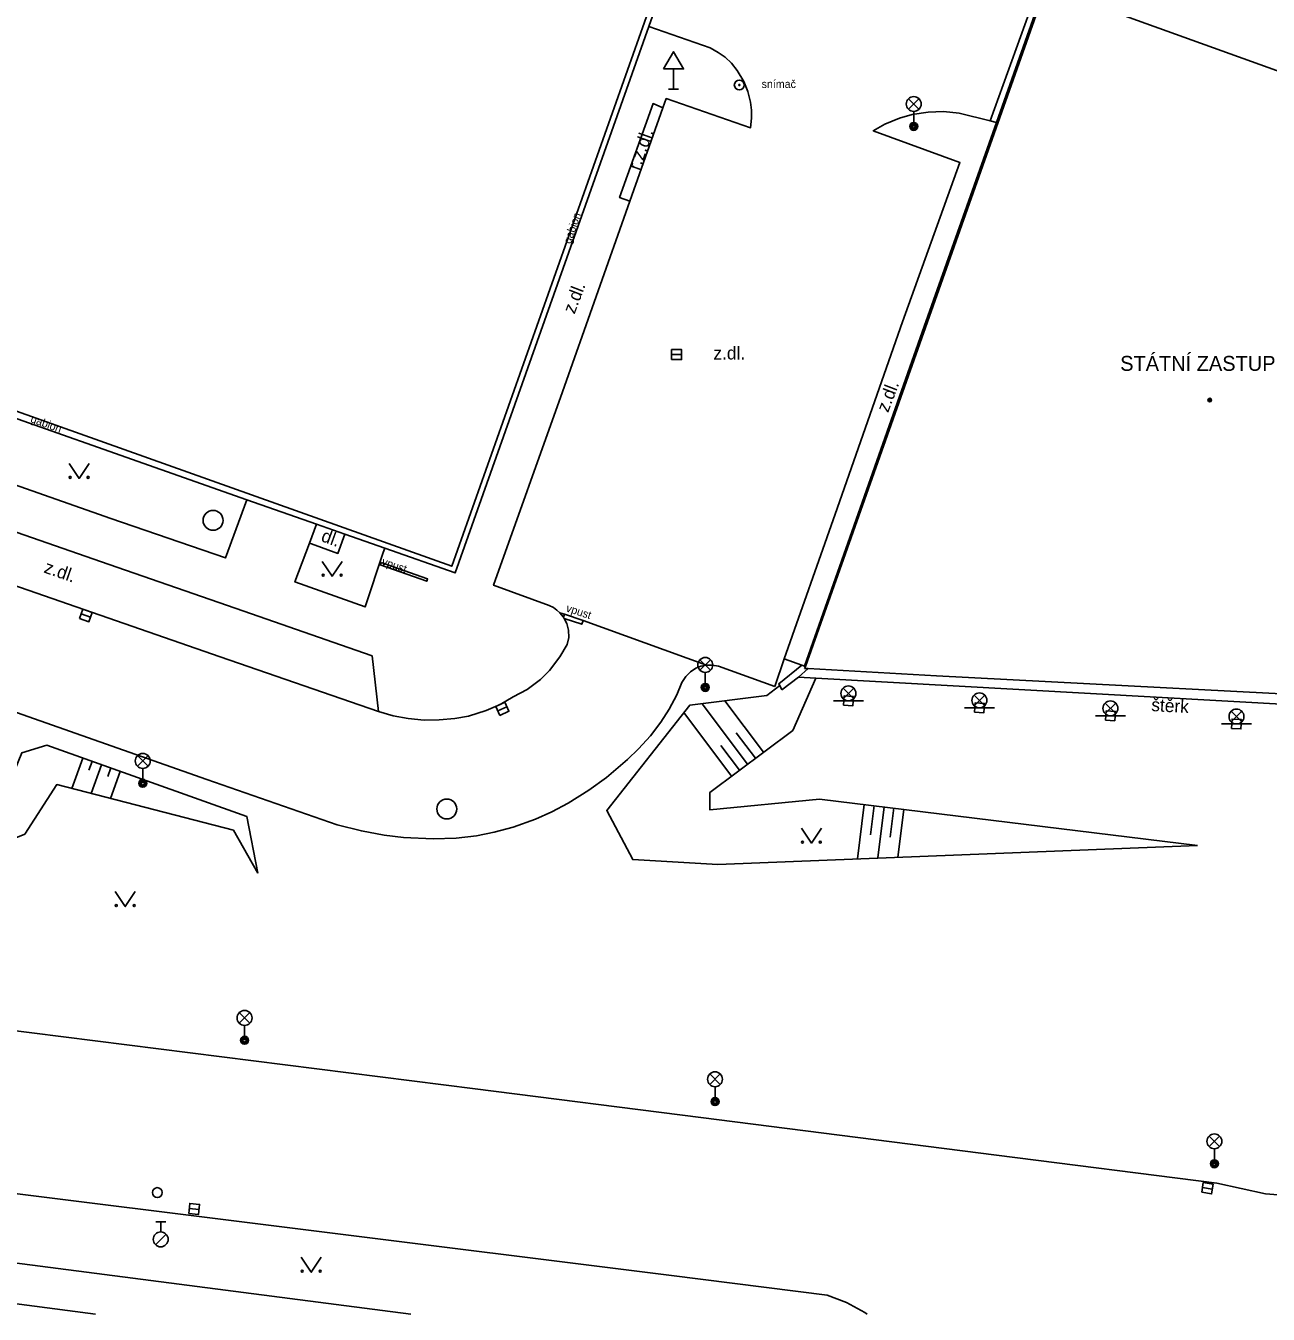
# Model space of a CAD drawing. Extents: x -598932 to -598196, y -1162207 to -1161504.
# Drawn here: x -598721.9 to -598659.5, y -1162207 to -1162142.2 of the extents above; entities that cross this region are included whole.
import ezdxf

# ---------------------------------------------------------------- set-up
doc = ezdxf.new("R2010")
doc.units = 0
for name, color, linetype in [('kanalizace - povrch.  znaky - skut. velikost', 7, 'Continuous'), ('Level 25', 7, 'Continuous'), ('Level 27', 7, 'Continuous'), ('Level 28', 7, 'Continuous'), ('Level 33', 7, 'Continuous'), ('Level 34', 7, 'Continuous'), ('Level 36', 7, 'Continuous'), ('Level 39', 7, 'Continuous'), ('TM - budovy zdene_ betonove - VP', 7, 'Continuous'), ('TM - chodniky - VP', 7, 'Continuous'), ('TM - dolni hrana svahu', 7, 'Continuous'), ('TM - horni hrana svahu', 7, 'Continuous'), ('TM - komunikace - VP', 7, 'Continuous'), ('TM - popis objektu', 7, 'Continuous'), ('TM - popis povrchu', 7, 'Continuous'), ('TM - poznamka', 7, 'Continuous'), ('TM - rozhrani ploch obecne - VP', 7, 'Continuous'), ('TM - srafovani', 7, 'Continuous'), ('TM - zed operna - VP', 7, 'Continuous')]:
    doc.layers.add(name, color=color, linetype=linetype)

msp = doc.modelspace()

# ---------------------------------------------------------------- linework, layer by layer
at = {"layer": 'kanalizace - povrch.  znaky - skut. velikost'}
for points in [[(-598704.1, -1162169.2), (-598704.14, -1162169.32), (-598701.81, -1162170.14), (-598701.77, -1162170.02), (-598704.1, -1162169.2)], [(-598694.94, -1162171.95), (-598694.89, -1162171.8)], [(-598694.89, -1162171.8), (-598693.96, -1162172.11)], [(-598693.96, -1162172.11), (-598694.02, -1162172.3), (-598694.9, -1162172.01)]]:
    msp.add_lwpolyline(points, dxfattribs=at)
at = {"layer": 'Level 25'}
for radius in [0.25, 0.0303]:
    msp.add_circle((-598686.11, -1162145.21), radius, dxfattribs=at)
at = {"layer": 'Level 27'}
for p, q in [((-598689.51, -1162158.75), (-598689.01, -1162158.75)), ((-598719.166, -1162171.778), (-598718.694, -1162171.942)), ((-598698.237, -1162176.655), (-598697.783, -1162176.445)), ((-598662.847, -1162200.589), (-598662.353, -1162200.671)), ((-598713.739, -1162201.645), (-598713.241, -1162201.695))]:
    msp.add_line(p, q, dxfattribs=at)
for points in [[(-598689.51, -1162159), (-598689.01, -1162159), (-598689.01, -1162158.5), (-598689.51, -1162158.5)], [(-598719.248, -1162172.014), (-598718.776, -1162172.178), (-598718.612, -1162171.706), (-598719.084, -1162171.542)], [(-598698.131, -1162176.882), (-598697.678, -1162176.671), (-598697.889, -1162176.218), (-598698.342, -1162176.429)], [(-598662.887, -1162200.836), (-598662.394, -1162200.917), (-598662.313, -1162200.424), (-598662.806, -1162200.343)], [(-598713.764, -1162201.893), (-598713.267, -1162201.944), (-598713.216, -1162201.447), (-598713.713, -1162201.396)]]:
    msp.add_lwpolyline(points, close=True, dxfattribs=at)
for centre in [(-598712.54, -1162167.08), (-598700.8, -1162181.58)]:
    msp.add_circle(centre, 0.5, dxfattribs=at)
at = {"layer": 'Level 28'}
for p, q in [((-598715.428, -1162203.472), (-598714.898, -1162202.942)), ((-598715.42, -1162202.325), (-598714.92, -1162202.325)), ((-598715.17, -1162202.825), (-598715.17, -1162202.325))]:
    msp.add_line(p, q, dxfattribs=at)
for centre, radius in [((-598715.34, -1162200.85), 0.25), ((-598715.17, -1162203.2), 0.375)]:
    msp.add_circle(centre, radius, dxfattribs=at)
at = {"layer": 'Level 33'}
for p, q in [((-598677.615, -1162146.43), (-598677.085, -1162145.9)), ((-598677.615, -1162145.9), (-598677.085, -1162146.43)), ((-598677.35, -1162146.54), (-598677.35, -1162147.29)), ((-598688.085, -1162174.61), (-598687.555, -1162174.08)), ((-598688.085, -1162174.08), (-598687.555, -1162174.61)), ((-598687.82, -1162174.72), (-598687.82, -1162175.47)), ((-598680.895, -1162176.04), (-598680.365, -1162175.51)), ((-598680.895, -1162175.51), (-598680.365, -1162176.04)), ((-598681.38, -1162176.15), (-598679.88, -1162176.15)), ((-598674.315, -1162176.39), (-598673.785, -1162175.86)), ((-598674.315, -1162175.86), (-598673.785, -1162176.39)), ((-598667.735, -1162176.79), (-598667.205, -1162176.26)), ((-598667.735, -1162176.26), (-598667.205, -1162176.79)), ((-598674.8, -1162176.5), (-598673.3, -1162176.5)), ((-598668.22, -1162176.9), (-598666.72, -1162176.9)), ((-598661.405, -1162177.2), (-598660.875, -1162176.67)), ((-598661.405, -1162176.67), (-598660.875, -1162177.2)), ((-598661.89, -1162177.31), (-598660.39, -1162177.31)), ((-598716.335, -1162179.43), (-598715.805, -1162178.9)), ((-598716.335, -1162178.9), (-598715.805, -1162179.43)), ((-598716.07, -1162179.54), (-598716.07, -1162180.29)), ((-598711.225, -1162192.34), (-598710.695, -1162191.81)), ((-598711.225, -1162191.81), (-598710.695, -1162192.34)), ((-598710.96, -1162192.45), (-598710.96, -1162193.2)), ((-598687.595, -1162195.42), (-598687.065, -1162194.89)), ((-598687.595, -1162194.89), (-598687.065, -1162195.42)), ((-598687.33, -1162195.53), (-598687.33, -1162196.28)), ((-598662.515, -1162198.54), (-598661.985, -1162198.01)), ((-598662.515, -1162198.01), (-598661.985, -1162198.54)), ((-598662.25, -1162198.65), (-598662.25, -1162199.4))]:
    msp.add_line(p, q, dxfattribs=at)
for centre, radius in [((-598677.35, -1162146.165), 0.375), ((-598677.35, -1162147.29), 0.2), ((-598677.35, -1162147.29), 0.145), ((-598677.35, -1162147.29), 0.0876), ((-598687.82, -1162174.345), 0.375), ((-598687.82, -1162175.47), 0.2), ((-598687.82, -1162175.47), 0.145), ((-598687.82, -1162175.47), 0.0876), ((-598680.63, -1162175.775), 0.375), ((-598674.05, -1162176.125), 0.375), ((-598667.47, -1162176.525), 0.375), ((-598661.14, -1162176.935), 0.375), ((-598716.07, -1162179.165), 0.375), ((-598716.07, -1162180.29), 0.2), ((-598716.07, -1162180.29), 0.145), ((-598716.07, -1162180.29), 0.0876), ((-598710.96, -1162192.075), 0.375), ((-598710.96, -1162193.2), 0.2), ((-598710.96, -1162193.2), 0.145), ((-598710.96, -1162193.2), 0.0876), ((-598687.33, -1162195.155), 0.375), ((-598687.33, -1162196.28), 0.2), ((-598687.33, -1162196.28), 0.145), ((-598687.33, -1162196.28), 0.0876), ((-598662.25, -1162198.275), 0.375), ((-598662.25, -1162199.4), 0.2), ((-598662.25, -1162199.4), 0.145), ((-598662.25, -1162199.4), 0.0876)]:
    msp.add_circle(centre, radius, dxfattribs=at)
at = {"layer": 'Level 34'}
for p, q in [((-598689.41, -1162144.402), (-598689.41, -1162145.42)), ((-598689.66, -1162145.42), (-598689.16, -1162145.42))]:
    msp.add_line(p, q, dxfattribs=at)
msp.add_lwpolyline([(-598689.91, -1162144.402), (-598688.91, -1162144.402), (-598689.41, -1162143.536)], close=True, dxfattribs=at)
at = {"layer": 'Level 36'}
for points in [[(-598719.77, -1162164.22), (-598719.27, -1162164.97), (-598718.77, -1162164.22)], [(-598707.06, -1162169.14), (-598706.56, -1162169.89), (-598706.06, -1162169.14)], [(-598682.99, -1162182.54), (-598682.49, -1162183.29), (-598681.99, -1162182.54)], [(-598717.45, -1162185.73), (-598716.95, -1162186.48), (-598716.45, -1162185.73)], [(-598708.11, -1162204.1), (-598707.61, -1162204.85), (-598707.11, -1162204.1)]]:
    msp.add_lwpolyline(points, dxfattribs=at)
for centre in [(-598719.72, -1162164.92), (-598718.821, -1162164.92), (-598707.01, -1162169.84), (-598706.111, -1162169.84), (-598682.94, -1162183.24), (-598682.041, -1162183.24), (-598717.4, -1162186.43), (-598716.501, -1162186.43), (-598708.06, -1162204.8), (-598707.161, -1162204.8)]:
    msp.add_circle(centre, 0.05, dxfattribs=at)
at = {"layer": 'Level 39'}
for radius in [0.09, 0.0398]:
    msp.add_circle((-598662.48, -1162161.04), radius, dxfattribs=at)
at = {"layer": 'TM - budovy zdene_ betonove - VP'}
for points in [[(-598728.07, -1162159.58), (-598700.55, -1162169.39), (-598688.31, -1162134.81)], [(-598642.61, -1162150.43), (-598670.34, -1162140.43)], [(-598670.91, -1162140.86), (-598682.79, -1162174.42)], [(-598682.79, -1162174.42), (-598682.83, -1162174.52)], [(-598682.83, -1162174.52), (-598682.65, -1162174.53)], [(-598682.65, -1162174.53), (-598676.21, -1162174.89)], [(-598676.21, -1162174.89), (-598651.82, -1162176.16)]]:
    msp.add_lwpolyline(points, dxfattribs=at)
at = {"layer": 'TM - chodniky - VP'}
for points in [[(-598703.92, -1162168.48), (-598700.38, -1162169.72), (-598690.66, -1162142.27)], [(-598682.84, -1162174.4), (-598676.83, -1162157.35), (-598673.2, -1162147.09)], [(-598673.2, -1162147.09), (-598673.51, -1162147.01)], [(-598727.85, -1162160.06), (-598710.85, -1162166.05)], [(-598710.85, -1162166.05), (-598711.92, -1162168.97), (-598717.68, -1162166.98), (-598727.11, -1162163.67), (-598729.18, -1162162.96)], [(-598710.85, -1162166.05), (-598707.34, -1162167.28)], [(-598707.34, -1162167.28), (-598705.93, -1162167.77)], [(-598707.7, -1162168.23), (-598707.6, -1162168.26), (-598706.27, -1162168.74), (-598705.93, -1162167.77)], [(-598705.93, -1162167.77), (-598703.92, -1162168.48)], [(-598703.92, -1162168.48), (-598703.99, -1162168.69), (-598704.9, -1162171.43), (-598708.43, -1162170.17), (-598707.7, -1162168.23)], [(-598683.86, -1162174.03), (-598682.97, -1162174.35)], [(-598682.97, -1162174.35), (-598682.84, -1162174.4)], [(-598680.88, -1162176.37), (-598680.85, -1162175.9), (-598680.38, -1162175.93), (-598680.41, -1162176.4), (-598680.88, -1162176.37)], [(-598674.3, -1162176.72), (-598674.27, -1162176.25), (-598673.8, -1162176.28), (-598673.83, -1162176.75), (-598674.3, -1162176.72)], [(-598667.72, -1162177.12), (-598667.69, -1162176.65), (-598667.22, -1162176.68), (-598667.25, -1162177.15), (-598667.72, -1162177.12)], [(-598661.39, -1162177.53), (-598661.36, -1162177.06), (-598660.89, -1162177.09), (-598660.92, -1162177.56), (-598661.39, -1162177.53)], [(-598738.95, -1162202.25), (-598702.604, -1162206.96)], [(-598739.5, -1162206.22), (-598739.28, -1162204.23), (-598718.442, -1162206.96)]]:
    msp.add_lwpolyline(points, dxfattribs=at)
at = {"layer": 'TM - dolni hrana svahu'}
for points in [[(-598710.29, -1162184.81), (-598711.52, -1162182.65), (-598720.39, -1162180.35), (-598722, -1162182.84), (-598723.92, -1162183.61), (-598735.43, -1162180.03), (-598736.48, -1162179.7), (-598749.81, -1162176.12), (-598751.67, -1162173.82), (-598751.7, -1162172.52), (-598751.75, -1162170.72), (-598755.24, -1162169.25), (-598759.12, -1162165.91), (-598763.29, -1162158.88), (-598765.05, -1162154.94), (-598768.37, -1162151.53)], [(-598663.09, -1162183.41), (-598687.19, -1162184.36), (-598691.46, -1162184.12), (-598692.77, -1162181.66), (-598688.6, -1162176.37), (-598684.72, -1162175.88), (-598684.08, -1162175.38)]]:
    msp.add_lwpolyline(points, dxfattribs=at)
at = {"layer": 'TM - horni hrana svahu'}
for points in [[(-598682.27, -1162175), (-598683.43, -1162177.63), (-598687.59, -1162180.75), (-598687.59, -1162181.63), (-598682.08, -1162181.08), (-598663.09, -1162183.41)], [(-598734.95, -1162178.48), (-598724.14, -1162182.16), (-598723.43, -1162181.89), (-598722.15, -1162178.76), (-598720.89, -1162178.38), (-598710.84, -1162181.96), (-598710.29, -1162184.81)]]:
    msp.add_lwpolyline(points, dxfattribs=at)
at = {"layer": 'TM - komunikace - VP'}
for points in [[(-598688.05, -1162134.9), (-598690.66, -1162142.27)], [(-598673.51, -1162147.01), (-598671.34, -1162140.99), (-598671.25, -1162140.73)], [(-598690.66, -1162142.27), (-598687.57, -1162143.34), (-598687.18, -1162143.57), (-598686.82, -1162143.81), (-598686.51, -1162144.12), (-598686.21, -1162144.48), (-598685.88, -1162145.04), (-598685.68, -1162145.54), (-598685.55, -1162146.08), (-598685.5, -1162146.48), (-598685.49, -1162146.87), (-598685.54, -1162147.36), (-598689.78, -1162145.89), (-598689.95, -1162146.36)], [(-598689.95, -1162146.36), (-598691.61, -1162151.05)], [(-598683.86, -1162174.03), (-598681.3, -1162166.77), (-598677.91, -1162157.11), (-598675.03, -1162149.11), (-598679.38, -1162147.51), (-598678.8, -1162147.18), (-598678.07, -1162146.87), (-598677.43, -1162146.69), (-598676.62, -1162146.57), (-598675.85, -1162146.55), (-598675.07, -1162146.63), (-598673.51, -1162147.01)], [(-598691.61, -1162151.05), (-598694.99, -1162160.63), (-598698.45, -1162170.34), (-598695.66, -1162171.36), (-598695.45, -1162171.46), (-598695.27, -1162171.59), (-598695.12, -1162171.72)], [(-598704.24, -1162176.69), (-598704.55, -1162173.89), (-598704.6, -1162173.87), (-598711, -1162171.65), (-598718.19, -1162169.15), (-598731.64, -1162164.47), (-598733.52, -1162166.53)], [(-598695.12, -1162171.72), (-598694.94, -1162171.95)], [(-598694.9, -1162172.01), (-598694.77, -1162172.27), (-598694.69, -1162172.6), (-598694.68, -1162172.97), (-598694.76, -1162173.31), (-598695.12, -1162173.93), (-598695.64, -1162174.62), (-598696.1, -1162175.08), (-598696.76, -1162175.57), (-598697.46, -1162175.95), (-598698.12, -1162176.33), (-598698.83, -1162176.63), (-598699.71, -1162176.91), (-598700.4, -1162177.04), (-598701.18, -1162177.1), (-598701.94, -1162177.11), (-598702.74, -1162177.03), (-598703.5, -1162176.9), (-598704.24, -1162176.69)], [(-598694.94, -1162171.95), (-598694.9, -1162172.01)], [(-598722.41, -1162176.74), (-598712.86, -1162180.1), (-598706.31, -1162182.38), (-598705.09, -1162182.68), (-598703.94, -1162182.89), (-598702.97, -1162183.01), (-598701.49, -1162183.08), (-598700.33, -1162183.05), (-598699.31, -1162182.92), (-598698.42, -1162182.74), (-598697.46, -1162182.49), (-598696.35, -1162182.09), (-598695.52, -1162181.72), (-598694.7, -1162181.29), (-598693.66, -1162180.64), (-598692.78, -1162180), (-598691.73, -1162179.1), (-598691.17, -1162178.55), (-598690.57, -1162177.9), (-598690.05, -1162177.22), (-598689.64, -1162176.57), (-598689.25, -1162175.84), (-598688.99, -1162175.23), (-598688.8, -1162174.92), (-598688.56, -1162174.69), (-598688.29, -1162174.51), (-598688.04, -1162174.4), (-598687.75, -1162174.35)], [(-598687.75, -1162174.35), (-598687.48, -1162174.35), (-598687.16, -1162174.41), (-598684.33, -1162175.42)], [(-598684.33, -1162175.42), (-598683.86, -1162174.03)], [(-598733.14, -1162191.48), (-598725.77, -1162192.35), (-598725.6, -1162191.81), (-598724.67, -1162191.93), (-598724.84, -1162192.43), (-598699.38, -1162195.64), (-598688.04, -1162197.08), (-598673.19, -1162198.97)], [(-598737.22, -1162199.04), (-598726.89, -1162200.32), (-598726.88, -1162201.01), (-598725.74, -1162201.14), (-598725.72, -1162200.49), (-598689.52, -1162205.02), (-598681.7, -1162206)], [(-598653.12, -1162201.05), (-598656.12, -1162201.19), (-598659.69, -1162200.91), (-598662.13, -1162200.38), (-598673.19, -1162198.97)], [(-598681.7, -1162206), (-598680.719, -1162206.376), (-598679.798, -1162206.881), (-598679.691, -1162206.96)]]:
    msp.add_lwpolyline(points, dxfattribs=at)
at = {"layer": 'TM - rozhrani ploch obecne - VP'}
for points in [[(-598673.2, -1162147.09), (-598670.98, -1162140.83)], [(-598689.95, -1162146.36), (-598690.44, -1162146.14), (-598692.12, -1162150.87), (-598691.61, -1162151.05)], [(-598638.85, -1162147.82), (-598640.51, -1162147.18), (-598651.38, -1162176.73), (-598682.27, -1162175)], [(-598733.52, -1162166.53), (-598712.19, -1162173.94), (-598704.24, -1162176.69)], [(-598707.7, -1162168.23), (-598707.34, -1162167.28)], [(-598695.12, -1162171.72), (-598694.89, -1162171.8)], [(-598693.96, -1162172.11), (-598687.75, -1162174.35)], [(-598684.08, -1162175.38), (-598684.13, -1162175.29), (-598682.97, -1162174.35)], [(-598682.84, -1162174.4), (-598682.79, -1162174.42)], [(-598682.27, -1162175), (-598683.14, -1162174.95)], [(-598683.97, -1162175.6), (-598684.08, -1162175.38)]]:
    msp.add_lwpolyline(points, dxfattribs=at)
at = {"layer": 'TM - srafovani'}
for points in [[(-598687.98, -1162176.29), (-598685.7, -1162179.33)], [(-598686.84, -1162176.15), (-598684.9, -1162178.73)], [(-598688.89, -1162176.74), (-598686.5, -1162179.93)], [(-598686.26, -1162177.76), (-598685.3, -1162179.03)], [(-598687.03, -1162178.39), (-598686.1, -1162179.63)], [(-598719.09, -1162179.02), (-598719.63, -1162180.55)], [(-598718.62, -1162179.19), (-598718.78, -1162179.63)], [(-598718.15, -1162179.36), (-598718.66, -1162180.8)], [(-598717.68, -1162179.52), (-598717.83, -1162179.94)], [(-598717.21, -1162179.69), (-598717.69, -1162181.05)], [(-598679.84, -1162181.35), (-598680.17, -1162184.08)], [(-598679.34, -1162181.41), (-598679.52, -1162182.87)], [(-598679.16, -1162184.04), (-598678.84, -1162181.47)], [(-598678.35, -1162181.53), (-598678.53, -1162183)], [(-598678.15, -1162184), (-598677.85, -1162181.6)]]:
    msp.add_lwpolyline(points, dxfattribs=at)
at = {"layer": 'TM - zed operna - VP'}
for points in [[(-598683.14, -1162174.95), (-598683.97, -1162175.6)], [(-598682.65, -1162174.53), (-598683.14, -1162174.95)]]:
    msp.add_lwpolyline(points, dxfattribs=at)

# ---------------------------------------------------------------- texts
at = {"layer": 'TM - popis objektu'}
msp.add_text('STÁTNÍ ZASTUPITELSTVÍ', height=0.75, dxfattribs=at).set_placement((-598666.98, -1162159.57))
at = {"layer": 'TM - popis povrchu'}
for s, rotation, p in [('r.z.dl.', 70.44599, (-598691.12, -1162149.54)), ('z.dl.', 69.03893, (-598694.39, -1162156.75)), ('z.dl.', 69.03893, (-598678.64, -1162161.7)), ('dl.', 340, (-598707.16, -1162168.11)), ('z.dl.', 340.84287, (-598721.08, -1162169.69)), ('štěrk', 356.8, (-598665.43, -1162176.66))]:
    msp.add_text(s, height=0.65, rotation=rotation, dxfattribs=at).set_placement(p)
msp.add_text('z.dl.', height=0.65, dxfattribs=at).set_placement((-598687.41, -1162159))
at = {"layer": 'TM - poznamka'}
msp.add_text('snímač', height=0.4, dxfattribs=at).set_placement((-598684.99, -1162145.36))
for s, rotation, p in [('gabion', 71, (-598694.58, -1162153.22)), ('gabion', 340, (-598721.74, -1162162.14)), ('vpust', 341, (-598704.1, -1162169.31)), ('vpust', 342, (-598694.84, -1162171.65))]:
    msp.add_text(s, height=0.4, rotation=rotation, dxfattribs=at).set_placement(p)

doc.saveas('drawing.dxf')
